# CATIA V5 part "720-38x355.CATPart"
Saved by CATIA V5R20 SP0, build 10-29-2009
Part number: 720-38x355
Definition: NONE
Nomenclature: 720-38x355
Source: Unknown
Description: 720-38x355
Bounding box of the stored display mesh (mm): x 0 to 355, y -19 to 19, z -19 to 19
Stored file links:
  C:\Users\Utente\Desktop\IO LAVORO\3D X SITO CF\X SITO\720\720-38x355.CATPart
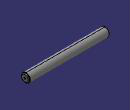
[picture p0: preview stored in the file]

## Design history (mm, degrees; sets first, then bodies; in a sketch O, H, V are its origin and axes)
Body1 "720-38x355" (main body)
  Solid1: solid without history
